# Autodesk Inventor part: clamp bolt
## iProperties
Author: Elise Moss
Created: 2001-09
Part Number: clamp bolt
Document SubType Name: Modeling
Designer: Elise Moss
Control State: 0
Master: False
Checked Out: False
PropertySet Name: Design Tracking Control
Length Units: 11272
Angle Units: 11279
Time Units: 11290
Mass Units: 11286
Shininess: 3
Angle Display Precision: 2
Document Length Units: 11272
Document Angle Units: 11286
Document Time Units: 11279
Document Mass Units: 11290
Document Length Units Precision: 3
Document Angle Units Precision: 0
Compacted: False
PropertySet Name: _Private Model Information
Density: 0.0
Volumn: 0.0
Area: 0.0
PropertySet Name: Model Information
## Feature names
1. Extrusion1
2. Hole1
3. Hole2
4. Revolution1
